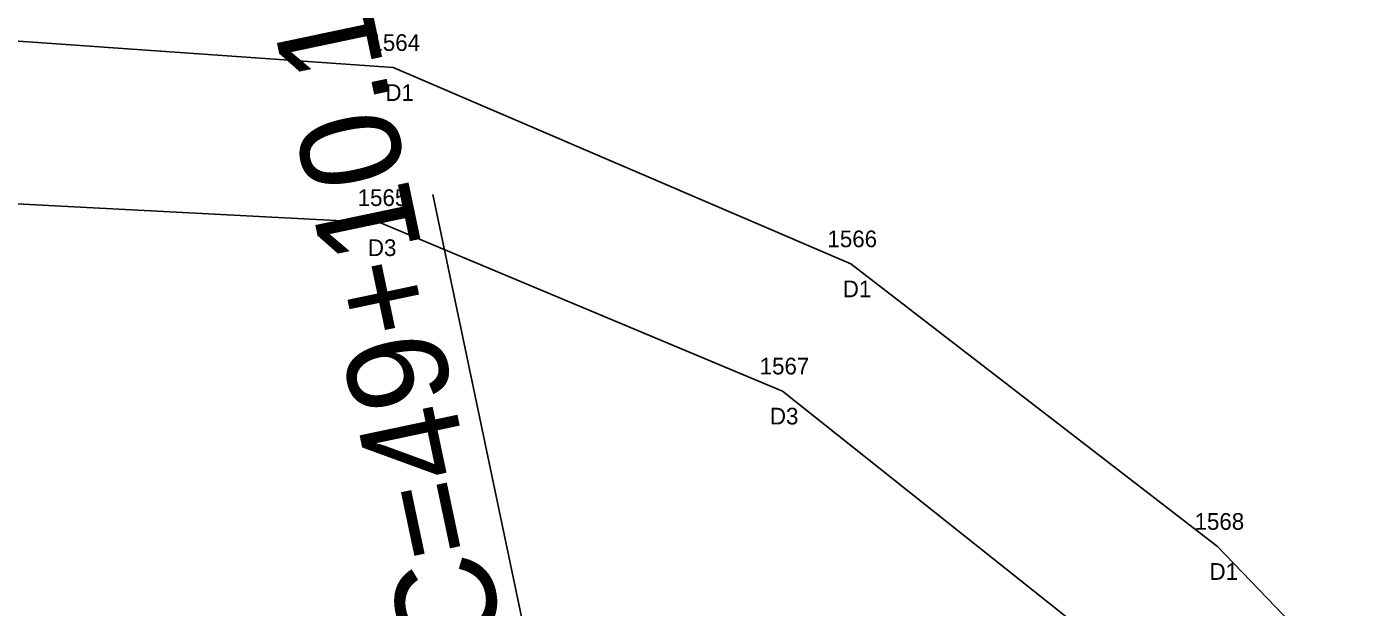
# Model space of a CAD drawing. Extents: x 1964982 to 1970452, y 1116335 to 1119906.
# Drawn here: x 1966640.1 to 1966719.9, y 1117494.1 to 1117528.9 of the extents above; entities that cross this region are included whole.
import ezdxf

# ---------------------------------------------------------------- set-up
doc = ezdxf.new("R2010")
doc.units = 0
for name, color, linetype in [('RD_EX_Driveway', 7, 'Continuous'), ('RD_EX_Driveway_txCode', 7, 'Continuous'), ('RD_HC_Data', 7, 'Continuous'), ('RD_PD_Final_TrvlWay', 7, 'Continuous'), ('RD_SMD_Locator', 7, 'Continuous')]:
    doc.layers.add(name, color=color, linetype=linetype)

msp = doc.modelspace()

# ---------------------------------------------------------------- linework, layer by layer
at = {"layer": 'RD_EX_Driveway'}
for points in [[(1966578.028, 1117435.239), (1966571.581, 1117480.753), (1966567.97, 1117515.311), (1966576.556, 1117516.6), (1966582.112, 1117483.547), (1966603.624, 1117509.102), (1966634.749, 1117528.345), (1966662.085, 1117526.43), (1966689.524, 1117514.663), (1966711.523, 1117497.722), (1966730.008, 1117478.512), (1966744.031, 1117462.693), (1966734.107, 1117458.19)], [(1966589.3, 1117436.331), (1966587.977, 1117456.65), (1966594.083, 1117483.042), (1966609.697, 1117504.074), (1966638.325, 1117518.314), (1966661.317, 1117517.134), (1966685.434, 1117507.038), (1966705.558, 1117491.043), (1966722.871, 1117472.119), (1966734.107, 1117458.19)]]:
    msp.add_lwpolyline(points, dxfattribs=at)
at = {"layer": 'RD_HC_Data'}
msp.add_line((1966684.871, 1117421.945), (1966664.447, 1117518.825), dxfattribs=at)
at = {"layer": 'RD_PD_Final_TrvlWay'}
msp.add_arc((1966373.74, 1118527.456), 1134.915, 281.904723, 295.046328, dxfattribs=at)
at = {"layer": 'RD_SMD_Locator'}
for centre in [(1966662.085, 1117526.43), (1966662.085, 1117526.43), (1966661.317, 1117517.134), (1966661.317, 1117517.134), (1966689.524, 1117514.663), (1966689.524, 1117514.663), (1966685.434, 1117507.038), (1966685.434, 1117507.038), (1966711.523, 1117497.722), (1966711.523, 1117497.722)]:
    msp.add_circle(centre, 0.001, dxfattribs=at)

# ---------------------------------------------------------------- texts
at = {"layer": 'RD_EX_Driveway_txCode'}
for s, p in [('1564', (1966660.715, 1117527.43)), ('1564', (1966660.715, 1117527.43)), ('D1', (1966661.612, 1117524.43)), ('D1', (1966661.612, 1117524.43)), ('1565', (1966659.947, 1117518.134)), ('1565', (1966659.947, 1117518.134)), ('D3', (1966660.561, 1117515.134)), ('D3', (1966660.561, 1117515.134)), ('1566', (1966688.13, 1117515.663)), ('1566', (1966688.13, 1117515.663)), ('D1', (1966689.051, 1117512.663)), ('D1', (1966689.051, 1117512.663)), ('1567', (1966684.064, 1117508.038)), ('1567', (1966684.064, 1117508.038)), ('D3', (1966684.678, 1117505.038)), ('D3', (1966684.678, 1117505.038)), ('1568', (1966710.153, 1117498.722)), ('1568', (1966710.153, 1117498.722)), ('D1', (1966711.05, 1117495.722)), ('D1', (1966711.05, 1117495.722))]:
    msp.add_text(s, height=1, dxfattribs=at).set_placement(p)
at = {"layer": 'RD_HC_Data'}
msp.add_text('PC=49+10.12', height=6, rotation=101.90472, dxfattribs=at).set_placement((1966669.912, 1117486.752))

doc.saveas('drawing.dxf')
